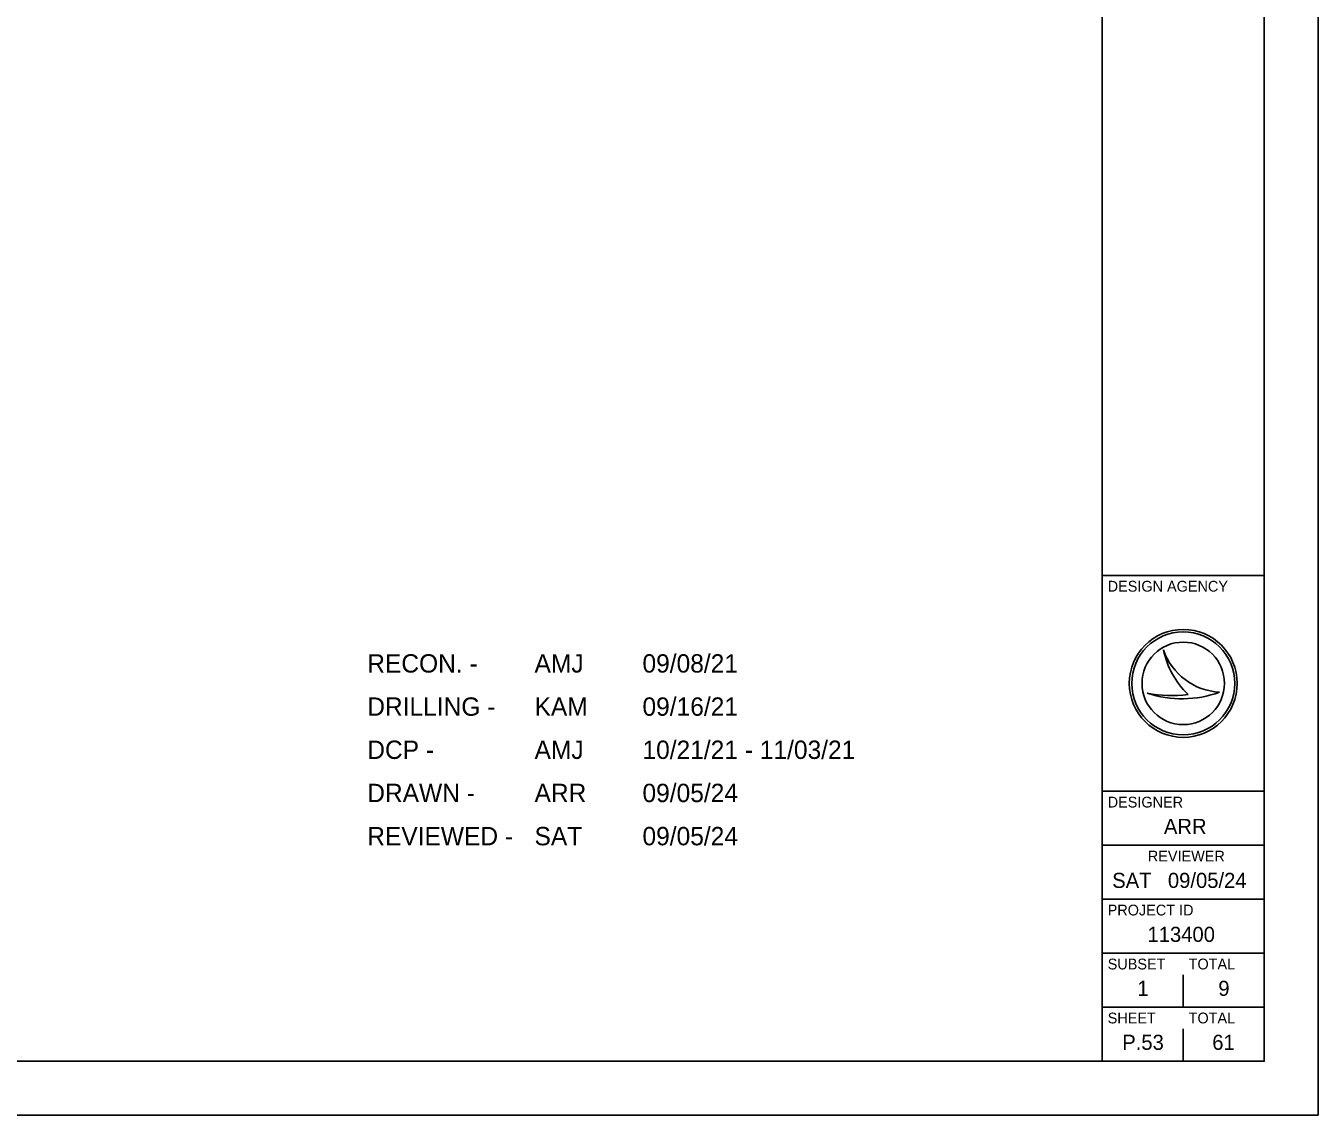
# Model space of a CAD drawing. Extents: x 0 to 34, y 0 to 26.1.
# Drawn here: x 22.03 to 34, y 0 to 10.09 of the extents above; entities that cross this region are included whole.
import ezdxf

# ---------------------------------------------------------------- set-up
doc = ezdxf.new("R2010")
doc.units = 0
for name, color, linetype in [('SH_Border', 7, 'Continuous'), ('SH_Cut_Line', 7, 'Continuous'), ('SH_Data', 7, 'Continuous'), ('SH_Text', 7, 'Continuous')]:
    doc.layers.add(name, color=color, linetype=linetype)

msp = doc.modelspace()

# ---------------------------------------------------------------- linework, layer by layer
at = {"layer": 'SH_Border'}
for p, q in [((32, 0.5), (32, 21.5)), ((32, 5), (33.5, 5)), ((32, 3), (33.5, 3)), ((32, 2.5), (33.5, 2.5)), ((32, 2), (33.5, 2)), ((32, 1.5), (33.5, 1.5)), ((32, 1), (33.5, 1))]:
    msp.add_line(p, q, dxfattribs=at)
msp.add_lwpolyline([(1.5, 21.5), (33.5, 21.5), (33.5, 0.5), (1.5, 0.5)], close=True, dxfattribs=at)
at = {"layer": 'SH_Cut_Line'}
msp.add_lwpolyline([(0, 0), (34, 0), (34, 22), (0, 22)], close=True, dxfattribs=at)
at = {"layer": 'SH_Data'}
for p, q in [((32.567, 4.31), (32.567, 4.31)), ((32.75, 4), (32.75, 4)), ((32.417, 3.91), (32.417, 3.91)), ((33.087, 3.919), (33.087, 3.919)), ((32.75, 1), (32.75, 1.3)), ((32.75, 0.5), (32.75, 0.8)), ((32.375, 0.675), (32.375, 0.675))]:
    msp.add_line(p, q, dxfattribs=at)
for radius in [0.5, 0.477, 0.477, 0.382]:
    msp.add_circle((32.75, 4), radius, dxfattribs=at)
for centre, radius, start, end in [((33.116, 4.498), 0.58, 198.9257, 198.9319), ((33.347, 4.47), 0.796, 191.6379, 191.6421), ((33.116, 4.498), 0.58, 198.9319, 267.1657), ((33.347, 4.47), 0.796, 191.6421, 226.0947), ((32.739, 4.87), 1.013, 251.4576, 290.0832), ((32.648, 5.154), 1.266, 259.4964, 259.4995), ((32.739, 4.87), 1.013, 251.4527, 251.4576), ((32.648, 5.154), 1.266, 259.4995, 276.6672)]:
    msp.add_arc(centre, radius, start, end, dxfattribs=at)

# ---------------------------------------------------------------- texts
for s, height, p in [('DESIGN AGENCY', 0.1, (32.05, 4.85)), ('DESIGNER', 0.1, (32.05, 2.85)), ('ARR', 0.14, (32.571, 2.605)), ('REVIEWER', 0.1, (32.422, 2.35)), ('SAT', 0.14, (32.092, 2.105)), ('09/05/24', 0.14, (32.608, 2.105)), ('PROJECT ID', 0.1, (32.05, 1.85)), ('SUBSET', 0.1, (32.05, 1.35)), ('TOTAL', 0.1, (32.8, 1.35)), ('1', 0.14, (32.325, 1.105)), ('9', 0.14, (33.075, 1.105)), ('SHEET', 0.1, (32.05, 0.85)), ('TOTAL', 0.1, (32.8, 0.85)), ('P.53', 0.14, (32.185, 0.605)), ('61', 0.14, (33.019, 0.605))]:
    msp.add_text(s, height=height, dxfattribs=at).set_placement(p)
at = {"layer": 'SH_Text'}
for s, height, p in [('RECON. -', 0.17, (25.19, 4.1)), ('AMJ', 0.17, (26.74, 4.1)), ('09/08/21', 0.17, (27.74, 4.1)), ('DRILLING -', 0.17, (25.19, 3.7)), ('KAM', 0.17, (26.74, 3.7)), ('09/16/21', 0.17, (27.74, 3.7)), ('DCP -', 0.17, (25.19, 3.3)), ('10/21/21 - 11/03/21', 0.17, (27.74, 3.3)), ('AMJ', 0.17, (26.74, 3.3)), ('DRAWN -', 0.17, (25.19, 2.9)), ('ARR', 0.17, (26.74, 2.9)), ('09/05/24', 0.17, (27.74, 2.9)), ('REVIEWED -', 0.17, (25.19, 2.5)), ('SAT', 0.17, (26.74, 2.5)), ('09/05/24', 0.17, (27.74, 2.5)), ('113400', 0.14, (32.419, 1.605))]:
    msp.add_text(s, height=height, dxfattribs=at).set_placement(p)

doc.saveas('drawing.dxf')
